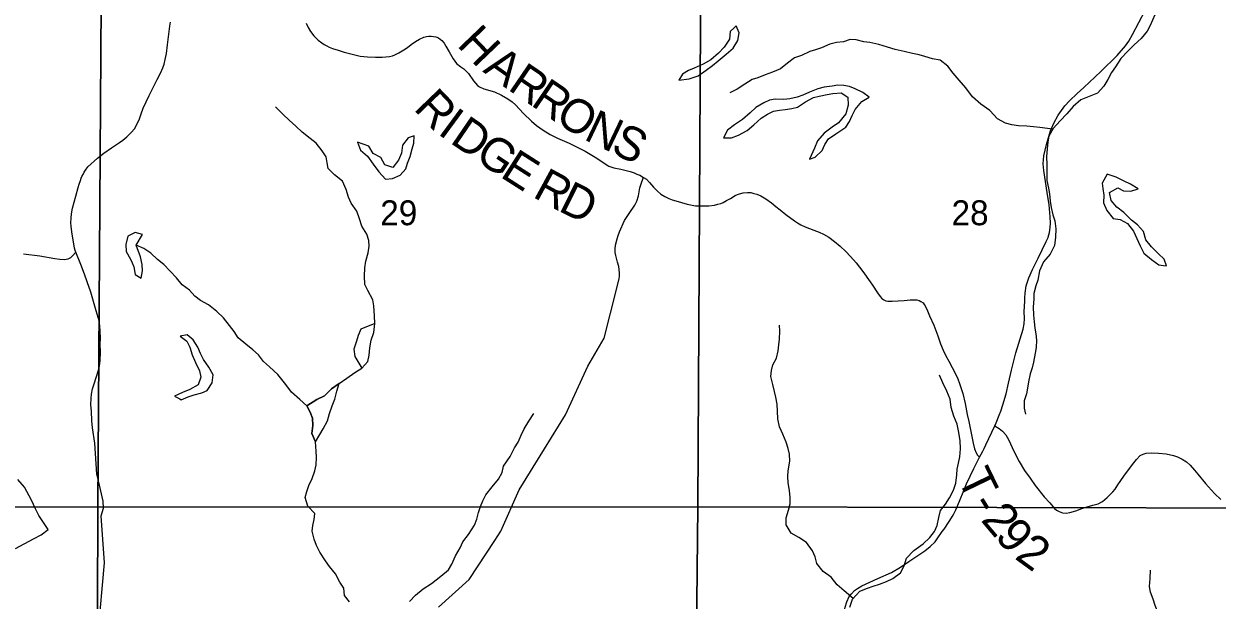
# Model space of a CAD drawing. Extents: x 0 to 34, y 0 to 22.
# Drawn here: x 5.667 to 7.673, y 19.478 to 20.447 of the extents above; entities that cross this region are included whole.
import ezdxf

# ---------------------------------------------------------------- set-up
doc = ezdxf.new("R2010")
doc.units = 0
for name, color, linetype in [('GM_X_County_Road', 7, 'Continuous'), ('GM_X_Minor_Lake', 7, 'Continuous'), ('GM_X_Minor_River', 7, 'Continuous'), ('GM_X_Section', 7, 'Continuous'), ('GM_X_Section_Text', 7, 'Continuous'), ('GM_X_Township_Road', 7, 'Continuous'), ('GM_X_Township_Road_Text', 7, 'Continuous')]:
    doc.layers.add(name, color=color, linetype=linetype)

msp = doc.modelspace()

# ---------------------------------------------------------------- linework, layer by layer
at = {"layer": 'GM_X_County_Road'}
for points in [[(7.3894, 20.0886), (7.3917, 20.096), (7.3927, 20.1044), (7.3935, 20.1121), (7.393, 20.1223), (7.3909, 20.1426), (7.3879, 20.1635), (7.3848, 20.1817), (7.382, 20.2006), (7.3812, 20.2116), (7.3821, 20.2248), (7.3864, 20.244), (7.3934, 20.2669), (7.3989, 20.2799), (7.4064, 20.2936), (7.4175, 20.3091), (7.4252, 20.3177), (7.4383, 20.3299), (7.4493, 20.34), (7.4782, 20.3668), (7.5052, 20.394), (7.5195, 20.4099), (7.5251, 20.4177), (7.5314, 20.4288), (7.5522, 20.4695)], [(7.3503, 19.9854), (7.3503, 19.9863), (7.3506, 19.9943), (7.3526, 20.0063), (7.3567, 20.0199), (7.3629, 20.0341), (7.3724, 20.0529), (7.3863, 20.0812), (7.3892, 20.0877), (7.3894, 20.0886)], [(7.2997, 19.7709), (7.3022, 19.7762), (7.3072, 19.789), (7.3101, 19.7959), (7.3133, 19.8065), (7.3186, 19.8247), (7.3228, 19.843), (7.3278, 19.8647), (7.335, 19.8939), (7.3474, 19.9336), (7.3488, 19.9424), (7.3497, 19.9514), (7.3493, 19.9632), (7.35, 19.9807), (7.3503, 19.9854)], [(7.274, 19.7186), (7.2794, 19.7287), (7.2817, 19.7331), (7.2849, 19.7393), (7.2997, 19.7709)], [(7.2113, 19.5932), (7.2143, 19.5974), (7.2228, 19.6104), (7.2295, 19.621), (7.2341, 19.6298), (7.2405, 19.6444), (7.2474, 19.6626), (7.252, 19.6738), (7.2642, 19.6993), (7.274, 19.7186)], [(7.037, 19.3891), (7.0373, 19.391), (7.0408, 19.4135), (7.0435, 19.433), (7.0461, 19.4553), (7.048, 19.4664), (7.0507, 19.4751), (7.0551, 19.4839), (7.0588, 19.4889), (7.0636, 19.4943), (7.0688, 19.4977), (7.0764, 19.5019), (7.0895, 19.5083), (7.1029, 19.5146), (7.1258, 19.5245), (7.1411, 19.5337), (7.1554, 19.543), (7.1821, 19.5609), (7.1913, 19.5681), (7.1993, 19.5761), (7.2026, 19.581), (7.2113, 19.5932)]]:
    msp.add_lwpolyline(points, dxfattribs=at)
at = {"layer": 'GM_X_Minor_Lake'}
for points in [[(6.7684, 20.3523), (6.7859, 20.3547), (6.801, 20.3597), (6.8143, 20.3692), (6.8249, 20.3772), (6.8347, 20.3849), (6.8483, 20.3959), (6.8601, 20.4062), (6.8676, 20.4188), (6.8702, 20.4317), (6.8648, 20.4434), (6.8614, 20.4401)], [(6.8614, 20.4401), (6.855, 20.4339), (6.8536, 20.421), (6.8445, 20.408), (6.835, 20.3978), (6.8222, 20.3863), (6.8093, 20.3791), (6.7945, 20.3725), (6.7847, 20.3683), (6.7748, 20.3626), (6.7684, 20.3523)], [(6.9881, 20.2197), (6.998, 20.2228), (7.0093, 20.2342), (7.0142, 20.2441), (7.0202, 20.2536), (7.0324, 20.262), (7.049, 20.2735), (7.0554, 20.283), (7.0599, 20.2929), (7.0652, 20.3031), (7.0762, 20.3165), (7.0883, 20.3237), (7.078, 20.3317), (7.0651, 20.3377), (7.0552, 20.3414), (7.0457, 20.3433), (7.0358, 20.344), (7.0263, 20.3424), (7.0126, 20.3405), (7.002, 20.3378), (6.9884, 20.332), (6.977, 20.327), (6.9672, 20.3236), (6.955, 20.3209), (6.9448, 20.3197), (6.9303, 20.3204), (6.9208, 20.3188), (6.9114, 20.3142), (6.8981, 20.3062), (6.8883, 20.2971), (6.8754, 20.286), (6.8622, 20.2772), (6.8504, 20.2684), (6.8437, 20.2555), (6.8521, 20.2555)], [(6.8521, 20.2555), (6.8573, 20.2556), (6.8687, 20.2598), (6.8835, 20.2674), (6.8948, 20.2773), (6.9069, 20.2884), (6.9175, 20.2953), (6.9278, 20.3003), (6.9376, 20.3018), (6.9475, 20.303), (6.9585, 20.3049), (6.968, 20.3069), (6.9812, 20.3157), (6.9949, 20.3233), (7.0044, 20.3256), (7.018, 20.328), (7.0275, 20.3299), (7.0415, 20.3311), (7.0526, 20.3236), (7.053, 20.3103), (7.0493, 20.2959), (7.0368, 20.2806), (7.0262, 20.273), (7.0126, 20.2631), (7.0017, 20.2501), (6.9968, 20.2379), (6.9881, 20.2197)], [(6.2285, 20.2479), (6.2335, 20.2346), (6.2449, 20.2244), (6.2549, 20.2108), (6.2644, 20.1983), (6.2755, 20.1858), (6.2872, 20.187), (6.3001, 20.1924), (6.3096, 20.2034), (6.3126, 20.2129), (6.3171, 20.224), (6.3204, 20.2369), (6.3231, 20.2464), (6.3234, 20.2589), (6.3169, 20.2564)], [(6.3169, 20.2564), (6.3135, 20.2551), (6.3041, 20.2429), (6.3022, 20.2296), (6.2974, 20.2178), (6.2875, 20.2052), (6.2742, 20.2101), (6.2677, 20.2222), (6.2548, 20.229), (6.2475, 20.2415), (6.2285, 20.2479)], [(7.5405, 20.1697), (7.5279, 20.1773), (7.5169, 20.1825), (7.5036, 20.1893), (7.4887, 20.1942), (7.4801, 20.1793), (7.4813, 20.1699), (7.4828, 20.1589), (7.4825, 20.1463), (7.4883, 20.1331), (7.4989, 20.1198), (7.5107, 20.118), (7.5225, 20.1112), (7.5328, 20.0984), (7.5386, 20.0862), (7.544, 20.0737), (7.5505, 20.0616), (7.5631, 20.0507), (7.5752, 20.0416), (7.5832, 20.0407)], [(7.5832, 20.0407), (7.5882, 20.0402), (7.5843, 20.0515), (7.5748, 20.0602), (7.563, 20.0719), (7.5538, 20.084), (7.5499, 20.0981), (7.5396, 20.109), (7.5293, 20.1169), (7.5168, 20.1298), (7.5046, 20.1388), (7.4954, 20.1498), (7.4927, 20.1635), (7.5063, 20.1715), (7.5158, 20.1662), (7.5284, 20.1659), (7.5405, 20.1697)], [(5.8563, 20.0746), (5.8669, 20.0926), (5.8547, 20.0959), (5.8422, 20.0898), (5.8389, 20.0758), (5.8397, 20.064), (5.8469, 20.0511), (5.8495, 20.0452)], [(5.8495, 20.0452), (5.8523, 20.0386), (5.8547, 20.0257), (5.8646, 20.0193), (5.8672, 20.0315), (5.8664, 20.0421), (5.8636, 20.0554), (5.8563, 20.0746)], [(6.2574, 19.943), (6.2341, 19.9337), (6.2295, 19.9231), (6.2269, 19.9132), (6.2224, 19.9003), (6.224, 19.8877), (6.2358, 19.8681)], [(6.2358, 19.8681), (6.246, 19.8795), (6.2478, 19.8902), (6.2489, 19.9023), (6.2515, 19.9152), (6.2556, 19.9281), (6.2574, 19.943)], [(5.9303, 19.9217), (5.9414, 19.9134), (5.9467, 19.9036), (5.9502, 19.8903), (5.9559, 19.8775), (5.9625, 19.8638), (5.9648, 19.8528), (5.9603, 19.8403), (5.9467, 19.8323), (5.9341, 19.8269), (5.9209, 19.8211), (5.9298, 19.8163)], [(5.9298, 19.8163), (5.9319, 19.8151), (5.9437, 19.8197), (5.9535, 19.8232), (5.9664, 19.8267), (5.9759, 19.8305), (5.9842, 19.8434), (5.9857, 19.8567), (5.9784, 19.8696), (5.9692, 19.8824), (5.9642, 19.8927), (5.96, 19.9033), (5.952, 19.9158), (5.9421, 19.9241), (5.9303, 19.9217)], [(6.1973, 19.8424), (6.1844, 19.8332), (6.1731, 19.8217), (6.1599, 19.8152), (6.1432, 19.8045), (6.149, 19.7943), (6.1528, 19.7841), (6.1533, 19.7715), (6.1515, 19.7582), (6.1577, 19.7442)], [(6.1577, 19.7442), (6.1706, 19.7661), (6.1782, 19.7798), (6.1815, 19.7916), (6.1856, 19.8049), (6.1901, 19.8159), (6.1935, 19.8292), (6.1973, 19.8424)]]:
    msp.add_lwpolyline(points, dxfattribs=at)
at = {"layer": 'GM_X_Minor_River'}
for points in [[(7.5687, 20.4624), (7.5609, 20.4442), (7.5557, 20.4347), (7.5455, 20.4221), (7.5337, 20.4118), (7.5235, 20.4008), (7.5118, 20.3886), (7.5028, 20.3749), (7.496, 20.365), (7.4899, 20.3532), (7.4832, 20.3422), (7.4726, 20.3303), (7.4585, 20.3246), (7.4445, 20.3192), (7.4317, 20.3082), (7.4207, 20.2956), (7.4094, 20.2838), (7.3976, 20.2712), (7.3905, 20.2583), (7.3886, 20.2488), (7.3875, 20.237), (7.3865, 20.2241), (7.3873, 20.2097), (7.387, 20.1975), (7.3874, 20.1835), (7.3897, 20.1706), (7.3917, 20.1611), (7.3929, 20.1486), (7.3944, 20.1384), (7.3975, 20.1259), (7.4006, 20.1156), (7.4022, 20.1023), (7.4015, 20.0883), (7.4, 20.0743), (7.3925, 20.0598), (7.3815, 20.0469), (7.3748, 20.0316), (7.3718, 20.0161), (7.3688, 20.0066), (7.3655, 19.9937), (7.3651, 19.9842), (7.364, 19.9713), (7.3649, 19.9572), (7.3657, 19.9462), (7.3672, 19.9352), (7.3688, 19.9257), (7.37, 19.9151), (7.3693, 19.9026), (7.3678, 19.8931), (7.3648, 19.8779), (7.3626, 19.8684), (7.3592, 19.8585), (7.3562, 19.8452), (7.3544, 19.8346), (7.3529, 19.8251), (7.3492, 19.8133), (7.3492, 19.8008), (7.3512, 19.7906)], [(7.3968, 20.2697), (7.3756, 20.2726), (7.365, 20.2737), (7.3536, 20.2748), (7.3395, 20.2755), (7.3281, 20.277), (7.3179, 20.28), (7.3045, 20.2875), (7.2912, 20.3011), (7.2763, 20.3117), (7.2622, 20.3241), (7.2511, 20.3392), (7.2397, 20.3521), (7.2298, 20.3638), (7.2206, 20.3759), (7.2076, 20.3861), (7.1947, 20.388), (7.1822, 20.3921), (7.1727, 20.3951), (7.1616, 20.3969), (7.1476, 20.4006), (7.132, 20.404), (7.1194, 20.4077), (7.1046, 20.4122), (7.0898, 20.4156), (7.0795, 20.4167), (7.0666, 20.42), (7.0567, 20.4204), (7.0453, 20.4169), (7.0336, 20.4157), (7.0226, 20.4126), (7.0082, 20.4069), (6.9983, 20.4034), (6.9888, 20.4003), (6.9748, 20.3938), (6.9631, 20.3896), (6.9513, 20.3808), (6.9392, 20.3713), (6.926, 20.3655), (6.9134, 20.3613), (6.9013, 20.3563), (6.8918, 20.3532), (6.8797, 20.3456), (6.8668, 20.3372), (6.8543, 20.3311)], [(6.1432, 19.8045), (6.1599, 19.8152), (6.1731, 19.8217), (6.1844, 19.8332), (6.1973, 19.8424), (6.2105, 19.8512), (6.2237, 19.8608), (6.2358, 19.8681), (6.246, 19.8795), (6.2478, 19.8902), (6.2489, 19.9023), (6.2515, 19.9152), (6.2556, 19.9281), (6.2574, 19.943), (6.2569, 19.9559), (6.256, 19.9729), (6.2544, 19.9828), (6.2456, 19.9987), (6.2406, 20.0089), (6.2401, 20.0225), (6.2408, 20.0369), (6.2426, 20.048), (6.2463, 20.062), (6.2478, 20.0734), (6.2473, 20.0829), (6.2438, 20.0935), (6.2354, 20.1067), (6.2319, 20.1192), (6.2273, 20.1321), (6.2177, 20.1453), (6.213, 20.1555), (6.2092, 20.1684), (6.203, 20.1824), (6.1896, 20.1929), (6.1793, 20.2039), (6.1774, 20.2134), (6.1754, 20.2232), (6.1689, 20.2334), (6.1589, 20.2466), (6.1486, 20.2541), (6.1356, 20.2651), (6.1249, 20.2749), (6.1135, 20.285), (6.1032, 20.2944), (6.0905, 20.3076)], [(6.2149, 19.4753), (6.2064, 19.4858), (6.2052, 19.498), (6.1987, 19.5085), (6.1914, 19.5221), (6.1814, 19.5346), (6.1745, 19.5444), (6.165, 19.5588), (6.1592, 19.5697), (6.1557, 19.5807), (6.1522, 19.594), (6.1533, 19.6038), (6.1555, 19.6137), (6.1566, 19.6236), (6.1451, 19.636), (6.1401, 19.6508), (6.1434, 19.6607), (6.1464, 19.6706), (6.152, 19.6827), (6.1565, 19.6957), (6.1591, 19.7056), (6.1594, 19.7181), (6.1589, 19.7287), (6.1577, 19.7442), (6.1515, 19.7582), (6.1533, 19.7715), (6.1528, 19.7841), (6.149, 19.7943), (6.1432, 19.8045), (6.1314, 19.8154), (6.1172, 19.8278), (6.108, 19.8407), (6.0947, 19.8573), (6.0805, 19.8705), (6.0702, 19.8795), (6.0622, 19.8905), (6.0526, 19.8987), (6.0408, 19.9082), (6.0278, 19.9191), (6.0209, 19.9296), (6.0132, 19.9398), (6.0029, 19.9527), (5.9918, 19.9636), (5.9781, 19.9745), (5.9644, 19.982), (5.9548, 19.9892), (5.946, 19.999), (5.9338, 20.0084), (5.9239, 20.0197), (5.9132, 20.031), (5.9028, 20.0423), (5.8921, 20.051), (5.8811, 20.0615), (5.8692, 20.069), (5.8563, 20.0746)], [(7.0616, 19.4809), (7.0467, 19.4939), (7.0348, 19.5037), (7.0245, 19.5166), (7.0111, 19.526), (7.0008, 19.5395), (6.9977, 19.5509), (6.9934, 19.5611), (6.9831, 19.5751), (6.9701, 19.5834), (6.9572, 19.5909), (6.9491, 19.6045), (6.949, 19.6162), (6.9531, 19.6292), (6.9557, 19.6402), (6.9556, 19.6504), (6.9544, 19.6622), (6.9521, 19.6751), (6.9516, 19.6857), (6.9523, 19.6955), (6.9552, 19.7115), (6.9544, 19.7233), (6.9521, 19.7331), (6.949, 19.7437), (6.9432, 19.757), (6.9378, 19.7694), (6.935, 19.7827), (6.9346, 19.796), (6.9341, 19.8074), (6.9314, 19.8191), (6.9294, 19.8286), (6.9263, 19.8407), (6.9232, 19.8543), (6.9242, 19.8642), (6.9265, 19.8737), (6.9328, 19.8847), (6.9358, 19.8973), (6.9365, 19.9072), (6.9379, 19.9167), (6.9382, 19.9303), (6.9378, 19.9402)], [(7.056, 19.4663), (7.0604, 19.4796), (7.0729, 19.493), (7.0857, 19.4984), (7.0952, 19.5015), (7.1058, 19.5049), (7.1179, 19.5096), (7.1282, 19.5146), (7.1414, 19.5241), (7.1474, 19.5359), (7.1511, 19.5489), (7.1635, 19.5615), (7.1794, 19.5729), (7.1904, 19.5833), (7.1983, 19.5936), (7.2028, 19.6038), (7.2057, 19.6171), (7.2083, 19.6289), (7.2166, 19.6396), (7.2233, 19.6499), (7.2305, 19.6632), (7.2342, 19.675), (7.2356, 19.689), (7.2367, 19.6985), (7.2385, 19.7084), (7.2407, 19.719), (7.2418, 19.7327), (7.2417, 19.7464), (7.2389, 19.7627), (7.2362, 19.774), (7.2308, 19.7873), (7.2265, 19.8017), (7.2245, 19.8157), (7.2191, 19.8293), (7.2126, 19.8433), (7.2068, 19.8565)], [(6.3159, 19.4755), (6.326, 19.4862), (6.3389, 19.4973), (6.3529, 19.5061), (6.3687, 19.5184), (6.3812, 19.5291), (6.3868, 19.5386), (6.3932, 19.5527), (6.4007, 19.566), (6.4052, 19.5763), (6.415, 19.5885), (6.4251, 19.6041), (6.4289, 19.614), (6.4318, 19.6254), (6.4352, 19.6357), (6.4389, 19.6452), (6.4442, 19.6551), (6.4547, 19.6688), (6.4653, 19.6814), (6.4713, 19.6928), (6.4738, 19.7031), (6.4851, 19.7194), (6.4922, 19.7339), (6.4983, 19.7438), (6.5035, 19.7556), (6.5084, 19.7659), (6.5163, 19.7788), (6.5249, 19.7918)], [(7.6838, 19.2568), (7.6693, 19.2692), (7.6579, 19.2824), (7.6494, 19.2922), (7.6425, 19.3024), (7.6341, 19.3175), (7.6302, 19.3293), (7.6237, 19.3425), (7.6152, 19.3595), (7.6094, 19.372), (7.6048, 19.3871), (7.5986, 19.4011), (7.5901, 19.4163), (7.5832, 19.4318), (7.5797, 19.442), (7.5755, 19.4533), (7.5693, 19.4692), (7.5658, 19.4798), (7.5616, 19.4912), (7.56, 19.501), (7.5606, 19.5147), (7.5617, 19.5287)]]:
    msp.add_lwpolyline(points, dxfattribs=at)
at = {"layer": 'GM_X_Section'}
for points in [[(4.5761, 20.6339), (5.7984, 20.651), (5.7918, 19.6342), (4.5644, 19.6379), (4.5646, 19.6808)], [(6.806, 20.65), (6.8002, 19.6351), (5.7918, 19.6342), (5.7984, 20.651)], [(6.806, 20.65), (7.8107, 20.6421), (7.8055, 19.6329), (6.8002, 19.6351)], [(5.7918, 19.6342), (5.7885, 18.6247), (5.7131, 18.626), (4.5473, 18.6426), (4.5644, 19.6379)], [(5.7918, 19.6342), (6.8002, 19.6351), (6.7897, 18.6209), (6.7712, 18.6214), (5.7885, 18.6247)], [(7.8055, 19.6329), (7.7955, 18.6195), (7.7667, 18.6191), (6.7897, 18.6209), (6.8002, 19.6351)]]:
    msp.add_lwpolyline(points, close=True, dxfattribs=at)
at = {"layer": 'GM_X_Township_Road'}
for points in [[(5.769, 20.1974), (5.7711, 20.2009), (5.7751, 20.2065), (5.7915, 20.2211), (5.8017, 20.2294), (5.8146, 20.2385), (5.8285, 20.2476), (5.8337, 20.2513), (5.8405, 20.257), (5.8479, 20.2641), (5.8532, 20.2707), (5.8576, 20.2776), (5.8621, 20.2875), (5.8648, 20.2957), (5.8682, 20.3051), (5.8781, 20.3267), (5.8864, 20.3432), (5.8916, 20.3532), (5.8971, 20.364), (5.9013, 20.3731), (5.9035, 20.3791), (5.9053, 20.3869), (5.9071, 20.3973), (5.9091, 20.4115), (5.9131, 20.4429), (5.9138, 20.4498)], [(6.1418, 20.4483), (6.1456, 20.4406), (6.1493, 20.4339), (6.1548, 20.4268), (6.1625, 20.4196), (6.1684, 20.4149), (6.1724, 20.4124), (6.1767, 20.41), (6.1808, 20.408), (6.1864, 20.4058), (6.1958, 20.4025), (6.2061, 20.3995), (6.233, 20.3926), (6.2453, 20.3913), (6.2585, 20.391), (6.2696, 20.391), (6.2761, 20.3913), (6.2821, 20.3922), (6.2871, 20.3934), (6.2911, 20.3949), (6.2981, 20.3983), (6.3061, 20.4032), (6.3123, 20.4072), (6.3188, 20.4121), (6.326, 20.4172), (6.3326, 20.4212), (6.3401, 20.4246), (6.3441, 20.4256), (6.3485, 20.4262), (6.3524, 20.4263), (6.3562, 20.4259), (6.3601, 20.4251), (6.3647, 20.4233), (6.3675, 20.4215), (6.3701, 20.4189), (6.3739, 20.4145), (6.3771, 20.4096), (6.3823, 20.4), (6.3889, 20.3882), (6.3917, 20.384), (6.395, 20.3803), (6.4022, 20.3747), (6.407, 20.3713), (6.4112, 20.3676), (6.4151, 20.3633), (6.4236, 20.3509), (6.4267, 20.347), (6.43, 20.3435), (6.4332, 20.3412), (6.4406, 20.3378), (6.4584, 20.3324), (6.4705, 20.3271), (6.4812, 20.3211), (6.4885, 20.3156), (6.4938, 20.3108), (6.5076, 20.2965), (6.5208, 20.2836), (6.5293, 20.276), (6.5405, 20.268), (6.5525, 20.2611), (6.5648, 20.2545), (6.584, 20.2462), (6.5955, 20.2407), (6.6111, 20.2328), (6.6279, 20.2228), (6.6509, 20.2079), (6.6541, 20.2065), (6.6595, 20.2049), (6.6713, 20.2024), (6.687, 20.1986), (6.6935, 20.1964), (6.6982, 20.1945), (6.7027, 20.1925), (6.7094, 20.1887), (6.7143, 20.1856), (6.7195, 20.1804), (6.7261, 20.1724), (6.7321, 20.1662), (6.7383, 20.1609), (6.7451, 20.1567), (6.7518, 20.1535), (6.7572, 20.1513), (6.7635, 20.1493), (6.7728, 20.1464), (6.7827, 20.144), (6.7963, 20.1411), (6.8088, 20.1408), (6.8192, 20.1411), (6.8283, 20.1421), (6.8343, 20.1436), (6.8393, 20.1451), (6.8433, 20.1468), (6.8486, 20.1498), (6.8552, 20.1536), (6.8634, 20.1583), (6.8671, 20.1601), (6.8704, 20.1613), (6.8768, 20.1631), (6.8838, 20.1635), (6.8893, 20.1632), (6.8945, 20.162), (6.8995, 20.1604), (6.9062, 20.1576), (6.9149, 20.1529), (6.9245, 20.1461), (6.9317, 20.1401), (6.9387, 20.1344), (6.9482, 20.1264), (6.9629, 20.1158), (6.9679, 20.1126), (6.9735, 20.1093), (6.9811, 20.1055), (6.9957, 20.1002), (7.0047, 20.0968), (7.0118, 20.0934), (7.0205, 20.0881), (7.0304, 20.0811), (7.0399, 20.0732), (7.0493, 20.064), (7.0569, 20.0559), (7.0666, 20.0449), (7.0778, 20.0308), (7.0904, 20.0134), (7.0942, 20.0079), (7.1025, 19.995), (7.1068, 19.9886), (7.1099, 19.9851), (7.1131, 19.9827), (7.1164, 19.9812), (7.1199, 19.9807), (7.1269, 19.9807), (7.1473, 19.9821), (7.1575, 19.9828), (7.1633, 19.9831), (7.1684, 19.9828), (7.1723, 19.982), (7.1756, 19.9804), (7.1792, 19.9779), (7.1811, 19.9753), (7.1826, 19.9726), (7.1865, 19.9643), (7.19, 19.956), (7.1971, 19.9406), (7.2038, 19.9224), (7.2085, 19.9091), (7.2128, 19.8982), (7.2173, 19.8886), (7.2223, 19.8801), (7.2283, 19.869), (7.2369, 19.8517), (7.2411, 19.8404), (7.2457, 19.8254), (7.2496, 19.8089), (7.2533, 19.7901), (7.2558, 19.7786), (7.2636, 19.742), (7.2658, 19.7322), (7.2681, 19.726), (7.2707, 19.7219), (7.274, 19.7186)], [(5.667, 20.0603), (5.6942, 20.0567), (5.7197, 20.0526), (5.7277, 20.0514), (5.7356, 20.0508), (5.7388, 20.0512), (5.742, 20.0521), (5.744, 20.0529), (5.7462, 20.0544), (5.7491, 20.0568), (5.7549, 20.0629), (5.7536, 20.0661), (5.7527, 20.0701), (5.7482, 20.0974), (5.7469, 20.1071), (5.7466, 20.1124), (5.7469, 20.1205), (5.7476, 20.1274), (5.7494, 20.137), (5.7551, 20.1572), (5.759, 20.1718), (5.7604, 20.1772), (5.7626, 20.1835), (5.764, 20.1875), (5.7651, 20.1901), (5.7675, 20.1948), (5.769, 20.1974)], [(6.4693, 19.5941), (6.5002, 19.6634), (6.5428, 19.7326), (6.5782, 19.7897), (6.6155, 19.8715), (6.643, 19.9187), (6.6642, 20.0028), (6.6683, 20.0191), (6.6688, 20.0223), (6.669, 20.0276), (6.6683, 20.034), (6.6675, 20.0388), (6.6652, 20.0465), (6.6625, 20.0575), (6.6617, 20.0624), (6.6615, 20.0685), (6.6623, 20.0749), (6.6649, 20.0855), (6.6663, 20.0909), (6.6688, 20.0972), (6.6773, 20.1161), (6.6853, 20.1283), (6.6945, 20.1419), (6.6977, 20.1491), (6.7005, 20.1579), (6.703, 20.1715), (6.7065, 20.1811), (6.7094, 20.1887)], [(5.7922, 19.4222), (5.8028, 19.5407), (5.7976, 19.6196), (5.8012, 19.6327), (5.8006, 19.6445), (5.7964, 19.6641), (5.7927, 19.6787), (5.7901, 19.6901), (5.787, 19.7421), (5.7829, 19.7675), (5.7816, 19.7794), (5.781, 19.7957), (5.7803, 19.8065), (5.7808, 19.8176), (5.7814, 19.8244), (5.7831, 19.8332), (5.7856, 19.8417), (5.7929, 19.8646), (5.7944, 19.8714), (5.7956, 19.8811), (5.7961, 19.8949), (5.796, 19.9078), (5.7961, 19.9188), (5.796, 19.9296), (5.7951, 19.939), (5.7938, 19.9479), (5.7891, 19.9645), (5.7799, 19.9956), (5.7741, 20.0132), (5.7694, 20.0263), (5.7634, 20.0423), (5.7549, 20.0629)], [(7.274, 19.7186), (7.2794, 19.7287), (7.2817, 19.7331), (7.2849, 19.7393), (7.2997, 19.7709)], [(7.2997, 19.7709), (7.307, 19.7665), (7.3129, 19.762), (7.3181, 19.7558), (7.3228, 19.7479), (7.3322, 19.7273), (7.3405, 19.7113), (7.3495, 19.6963), (7.3589, 19.6831), (7.3675, 19.6708), (7.3829, 19.652), (7.392, 19.6415), (7.4002, 19.632), (7.4035, 19.6293), (7.4079, 19.6271), (7.4136, 19.625), (7.4195, 19.6245), (7.4261, 19.6254), (7.4357, 19.628), (7.4461, 19.6319), (7.4552, 19.635), (7.4643, 19.6378), (7.4733, 19.6401), (7.481, 19.6441), (7.4888, 19.6508), (7.498, 19.6601), (7.5018, 19.6644), (7.5065, 19.6719), (7.5166, 19.6864), (7.5314, 19.7062), (7.5378, 19.7143), (7.5443, 19.721), (7.5493, 19.7235), (7.5543, 19.725), (7.5639, 19.7255), (7.5748, 19.7253), (7.5879, 19.7238), (7.6002, 19.7212), (7.607, 19.7189), (7.6145, 19.7151), (7.6217, 19.7106), (7.6279, 19.7049), (7.6355, 19.6965), (7.6408, 19.6896), (7.6537, 19.6743), (7.669, 19.6575), (7.6797, 19.6472)], [(5.6533, 19.5651), (5.6837, 19.5814), (5.6965, 19.5878), (5.7085, 19.5966), (5.6925, 19.6205), (5.6873, 19.6315), (5.6804, 19.6461), (5.6686, 19.6681), (5.6572, 19.681)], [(6.3644, 19.4665), (6.4158, 19.5127), (6.459, 19.5785), (6.4693, 19.5941)]]:
    msp.add_lwpolyline(points, dxfattribs=at)

# ---------------------------------------------------------------- texts
at = {"layer": 'GM_X_Section_Text'}
for s, p in [('29', (6.2666, 20.1084)), ('28', (7.227, 20.1084))]:
    msp.add_text(s, height=0.04186, rotation=0, dxfattribs=at).set_placement(p)
at = {"layer": 'GM_X_Township_Road_Text'}
for s, rotation, p in [('H', 313.7171, (6.3941, 20.4109)), ('A', 324.6306, (6.4376, 20.3671)), ('R', 325.725, (6.4794, 20.3374)), ('R', 325.721, (6.5179, 20.3111)), ('R', 313.8408, (6.3212, 20.3038)), ('O', 327.5975, (6.5582, 20.2837)), ('I', 323.6405, (6.3615, 20.2631)), ('N', 334.5825, (6.607, 20.2533)), ('D', 325.686, (6.3821, 20.248)), ('S', 333.5709, (6.6519, 20.232)), ('G', 325.8624, (6.4235, 20.2197)), ('E', 327.4897, (6.4664, 20.1907)), ('R', 331.4837, (6.521, 20.1568)), ('D', 333.5403, (6.564, 20.1335)), ('T', 295.8061, (7.236, 19.6833)), ('-', 301.7048, (7.2575, 19.6394)), ('2', 309.9701, (7.275, 19.6124)), ('9', 310.9558, (7.2982, 19.5847)), ('2', 323.8504, (7.3314, 19.5489))]:
    msp.add_text(s, height=0.0568, rotation=rotation, dxfattribs=at).set_placement(p)

doc.saveas('drawing.dxf')
